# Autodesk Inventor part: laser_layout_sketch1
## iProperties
Shininess: 64.0
Length Units: 11269
Angle Units: 11279
Time Units: 11290
Mass Units: 11283
Length Display Precision: 3
Angle Display Precision: 2
Compacted: True
Part Number: laser_layout_sketch1
Document SubType Name: Modeling
Created: 2004-08
Designer: John Blackburn
Manufacturer: Standard
Standards Organization: Custom
Density: 0.0
Volumn: 0.0
Area: 0.0
PropertySet Name: Model Information
Control State: 0
Master: False
Checked Out: False
Author: John Blackburn
